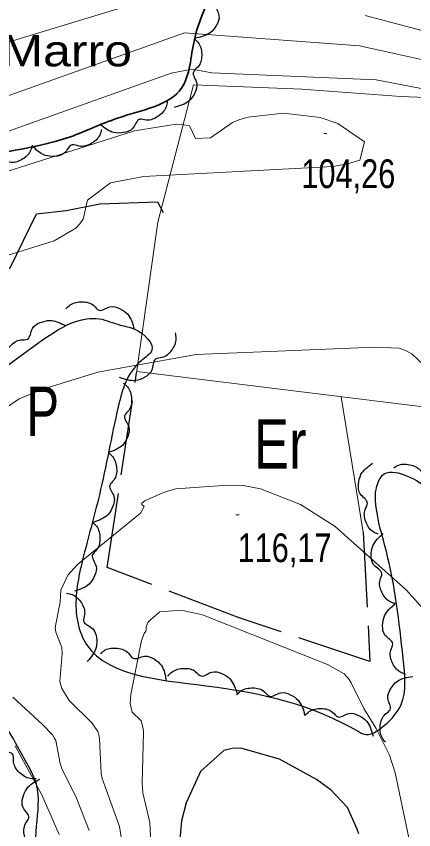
# Model space of a CAD drawing. Extents: x 483843 to 488449, y 4381269 to 4384483.
# Drawn here: x 486707.3 to 486828.4, y 4383075.2 to 4383322.9 of the extents above; entities that cross this region are included whole.
import ezdxf
from ezdxf.enums import TextEntityAlignment as Align

# ---------------------------------------------------------------- set-up
doc = ezdxf.new("R2010")
doc.units = 0
doc.header["$LTSCALE"] = 3.8
doc.linetypes.add('LONG_DASHED', pattern=[7.5, 6, -1.5])
for name, color, linetype, lineweight in [('13', 7, 'Continuous', 35), ('25', 7, 'LONG_DASHED', 25), ('27', 7, 'Continuous', 25), ('51', 7, 'Continuous', 13), ('7', 7, 'Continuous', 13), ('8', 7, 'Continuous', 25), ('9', 7, 'Continuous', 13)]:
    doc.layers.add(name, color=color, linetype=linetype, lineweight=lineweight)
doc.layers.add('31', color=7, linetype='Continuous')
doc.layers.add('5', color=7, linetype='Continuous')

msp = doc.modelspace()

# ---------------------------------------------------------------- linework, layer by layer
at = {"layer": '13'}
msp.add_spline([(486780.88, 4383404.79), (486794.13, 4383455.03), (486806.75, 4383492.74), (486812.33, 4383499.64), (486814.71, 4383503.51), (486819.41, 4383506.81), (486825.21, 4383508.61), (486829.49, 4383508.62), (486831.66, 4383508.22), (486834.79, 4383506.67), (486839.23, 4383502.48), (486841.25, 4383491.57), (486838.33, 4383465.65), (486835.59, 4383431.7), (486834, 4383420.31), (486833.25, 4383414.77), (486832.97, 4383406.37), (486832.3, 4383401.5), (486829.47, 4383397.12), (486823.83, 4383396.67), (486809.94, 4383396.27), (486802.97, 4383396.6), (486796, 4383397.37), (486791.44, 4383398.19), (486788.79, 4383396.8), (486785.88, 4383392.64), (486784.6, 4383386.95), (486784.53, 4383376.98), (486784.84, 4383372.17), (486782.2, 4383361.03), (486774.71, 4383351.45), (486769.08, 4383335.85), (486761.59, 4383315.77), (486757.7, 4383301.05), (486738.21, 4383291.87), (486723.87, 4383286.22), (486684.72, 4383277.1), (486662.99, 4383268.56), (486648.14, 4383263.67), (486639.3, 4383259.75), (486632.91, 4383279.8), (486638.33, 4383280.62), (486654.82, 4383284.96), (486667.34, 4383289.06), (486684.49, 4383297.14), (486691.09, 4383302.53), (486696.41, 4383307.18), (486694.82, 4383316.43), (486684.24, 4383321.46), (486669.01, 4383321.68), (486655.38, 4383318.57), (486643.48, 4383310.34), (486629.22, 4383315.27), (486629.5, 4383324.04), (486622.3, 4383324.82), (486616.85, 4383326.7), (486612.21, 4383337.87), (486614.37, 4383347.45), (486644.42, 4383349.27), (486649.2, 4383384.92), (486651.66, 4383388.63), (486652.89, 4383395.9), (486652.14, 4383401.38), (486671.78, 4383415.81), (486678.55, 4383411.44), (486675.33, 4383401.28), (486669.84, 4383395.35), (486659.1, 4383373.67), (486670.12, 4383362.71), (486675.25, 4383359.48), (486683.36, 4383359.82), (486702.12, 4383364.88), (486729.49, 4383379.19), (486744.12, 4383389.71), (486750.48, 4383393.52), (486749.77, 4383396.53), (486731.96, 4383399.94), (486712.51, 4383419.8), (486725.33, 4383419.24), (486752.3, 4383411.05), (486765.39, 4383408.24), (486770.85, 4383407.04), (486780.7, 4383403.07)], degree=3, dxfattribs=at)
at = {"layer": '25'}
for points in [[(486625.97, 4383203.81), (486659.6, 4383225.99), (486699.78, 4383243.65), (486705.44, 4383246.34), (486713.56, 4383262.73), (486722.5, 4383263.73), (486732.81, 4383265.76), (486750.38, 4383266.41), (486752.13, 4383263.16)], [(486813.02, 4383165.79), (486815.08, 4383126.44), (486775.28, 4383139.77), (486735.05, 4383155.05), (486744, 4383214.28)]]:
    msp.add_lwpolyline(points, dxfattribs=at)
at = {"layer": '27'}
for points in [[(486769.34, 4383336.54), (486770.46, 4383335.16), (486771.14, 4383331.43), (486769.74, 4383328.01), (486768.28, 4383326.57), (486769.09, 4383323.11), (486768.34, 4383320.22), (486766.42, 4383317.89), (486761.75, 4383316.21)], [(486761.71, 4383315.92), (486762.92, 4383314.62), (486763.83, 4383310.94), (486762.66, 4383307.44), (486761.29, 4383305.91), (486762.32, 4383302.51), (486761.75, 4383299.58), (486759.99, 4383297.12), (486755.44, 4383295.15)], [(486753.32, 4383297.03), (486752.97, 4383295.29), (486750.51, 4383292.4), (486746.98, 4383291.31), (486744.94, 4383291.54), (486742.77, 4383288.72), (486740.06, 4383287.47), (486737.04, 4383287.48), (486732.78, 4383290.03)], [(486733.3, 4383288.41), (486732.77, 4383286.72), (486730.04, 4383284.09), (486726.42, 4383283.36), (486724.41, 4383283.79), (486721.97, 4383281.2), (486719.14, 4383280.24), (486716.14, 4383280.55), (486712.16, 4383283.51)], [(486712.16, 4383283.52), (486711.63, 4383281.82), (486708.9, 4383279.19), (486705.28, 4383278.46), (486703.27, 4383278.88), (486700.84, 4383276.29), (486698.02, 4383275.32), (486695.01, 4383275.62), (486691.03, 4383278.59)], [(486722.48, 4383233.81), (486723.78, 4383235.02), (486727.46, 4383235.95), (486730.96, 4383234.79), (486732.5, 4383233.42), (486735.89, 4383234.47), (486738.83, 4383233.9), (486741.29, 4383232.15), (486743.27, 4383227.6)], [(486510.56, 4382972.83), (486592.89, 4382960.7), (486601.82, 4382957.51), (486605.65, 4382949.21), (486605.01, 4382945.38), (486612.67, 4382941.55), (486617.14, 4382941.55), (486645.86, 4382947.29), (486666.92, 4382951.76), (486682.87, 4382958.79), (486691.17, 4382972.2), (486697.55, 4382995.18), (486698.19, 4383013.7), (486700.1, 4383028.38), (486705.21, 4383044.98), (486712.23, 4383062.86), (486713.51, 4383076.27), (486713.51, 4383089.04), (486710.95, 4383094.79), (486707.76, 4383100.53), (486695, 4383117.13), (486669.47, 4383126.71), (486659.9, 4383138.2), (486650.96, 4383150.33), (486637.56, 4383166.93), (486626.71, 4383177.15), (486626.71, 4383182.26), (486685.43, 4383205.88), (486717.33, 4383225.68), (486728.82, 4383230.78), (486732.65, 4383230.78), (486739.03, 4383228.87), (486743.5, 4383227.59), (486748.61, 4383221.21), (486745.41, 4383218.01), (486738.39, 4383203.97), (486732.65, 4383177.15), (486727.55, 4383157.36), (486725.63, 4383141.39), (486727.55, 4383133.73), (486765.2, 4383119.05), (486811.79, 4383105), (486813.06, 4383104.36), (486819.44, 4383106.92), (486824.55, 4383113.3), (486825.19, 4383127.35), (486820.08, 4383159.91), (486816.89, 4383173.96), (486816.89, 4383178.43), (486819.44, 4383183.54), (486826.46, 4383182.9), (486839.23, 4383173.96), (486851.35, 4383158.63), (486851.35, 4383155.44), (486854.55, 4383149.7), (486860.29, 4383146.5), (486874.33, 4383147.78), (486881.35, 4383147.78), (486885.18, 4383146.5), (486885.82, 4383140.12), (486878.16, 4383135.65), (486855.18, 4383117.77), (486850.08, 4383106.92), (486844.33, 4383092.87), (486846.25, 4383073.72), (486850.08, 4383059.67), (486853.27, 4383048.81), (486859.01, 4383039.24), (486866.03, 4383030.3), (486874.97, 4383020.08), (486875.61, 4383011.78), (486873.05, 4382997.74), (486873.05, 4382979.86), (486877.52, 4382957.51), (486880.71, 4382931.33), (486896.03, 4382901.96), (486916.45, 4382878.98), (486920.28, 4382878.34), (486934.96, 4382878.98), (486953.46, 4382889.19), (486954.74, 4382904.52), (486949.64, 4382917.29), (486943.25, 4382926.22), (486931.13, 4382935.16), (486926.66, 4382940.27), (486927.94, 4382947.29), (486935.6, 4382954.32), (486935.6, 4382959.43), (486931.77, 4382975.39), (486917.73, 4383017.53), (486919, 4383028.38)], [(486703.82, 4383217.39), (486703.78, 4383219.16), (486705.55, 4383222.52), (486708.75, 4383224.36), (486710.79, 4383224.59), (486712.28, 4383227.82), (486714.66, 4383229.62), (486717.61, 4383230.28), (486722.32, 4383228.73)], [(486755.72, 4383226.52), (486755.98, 4383224.76), (486754.65, 4383221.2), (486751.71, 4383218.98), (486749.71, 4383218.49), (486748.64, 4383215.1), (486746.51, 4383213.01), (486743.67, 4383211.98), (486738.8, 4383212.93)], [(486739.95, 4383211.23), (486741.26, 4383210.03), (486742.47, 4383206.44), (486741.59, 4383202.85), (486740.34, 4383201.22), (486741.65, 4383197.91), (486741.32, 4383194.94), (486739.76, 4383192.35), (486735.38, 4383190.02)], [(486735.39, 4383190.02), (486736.7, 4383188.82), (486737.92, 4383185.23), (486737.04, 4383181.64), (486735.8, 4383180), (486737.11, 4383176.7), (486736.79, 4383173.73), (486735.24, 4383171.14), (486730.86, 4383168.8)], [(486817.6, 4383165.19), (486816, 4383165.97), (486813.8, 4383169.06), (486813.62, 4383172.75), (486814.33, 4383174.67), (486812.13, 4383177.46), (486811.6, 4383180.4), (486812.34, 4383183.33), (486815.86, 4383186.82)], [(486822.33, 4383185.43), (486823.9, 4383186.26), (486827.69, 4383186.22), (486830.78, 4383184.19), (486831.91, 4383182.48), (486835.46, 4383182.62), (486838.15, 4383181.32), (486840.08, 4383178.99), (486840.83, 4383174.09)], [(486730.52, 4383168.88), (486731.78, 4383167.63), (486732.84, 4383163.98), (486731.81, 4383160.44), (486730.51, 4383158.85), (486731.68, 4383155.5), (486731.22, 4383152.55), (486729.56, 4383150.02), (486725.09, 4383147.87)], [(486822.78, 4383144.05), (486821.12, 4383144.68), (486818.66, 4383147.57), (486818.15, 4383151.22), (486818.7, 4383153.2), (486816.26, 4383155.79), (486815.46, 4383158.67), (486815.95, 4383161.65), (486819.15, 4383165.44)], [(486722.64, 4383147.23), (486724.36, 4383146.82), (486727.17, 4383144.27), (486728.15, 4383140.71), (486727.87, 4383138.68), (486730.62, 4383136.43), (486731.77, 4383133.68), (486731.68, 4383130.66), (486728.99, 4383126.48)], [(486825.88, 4383122.57), (486824.23, 4383123.24), (486821.85, 4383126.2), (486821.43, 4383129.86), (486822.03, 4383131.83), (486819.66, 4383134.48), (486818.94, 4383137.38), (486819.51, 4383140.35), (486822.8, 4383144.05)], [(486733.04, 4383128.89), (486734.47, 4383129.95), (486738.22, 4383130.47), (486741.58, 4383128.94), (486742.96, 4383127.41), (486746.45, 4383128.08), (486749.3, 4383127.2), (486751.56, 4383125.18), (486753.03, 4383120.45)], [(486753.55, 4383121.99), (486754.8, 4383123.25), (486758.43, 4383124.34), (486761.98, 4383123.33), (486763.57, 4383122.03), (486766.92, 4383123.21), (486769.88, 4383122.78), (486772.41, 4383121.13), (486774.59, 4383116.67)], [(486819.85, 4383101.84), (486818.78, 4383103.25), (486818.22, 4383107), (486819.72, 4383110.37), (486821.23, 4383111.76), (486820.53, 4383115.25), (486821.38, 4383118.11), (486823.37, 4383120.39), (486828.09, 4383121.91)], [(486774.47, 4383116.27), (486775.78, 4383117.47), (486779.46, 4383118.39), (486782.96, 4383117.23), (486784.49, 4383115.86), (486787.89, 4383116.89), (486790.82, 4383116.33), (486793.28, 4383114.57), (486795.25, 4383110.02)], [(486795.25, 4383110.01), (486796.56, 4383111.21), (486800.24, 4383112.13), (486803.74, 4383110.95), (486805.27, 4383109.58), (486808.67, 4383110.61), (486811.6, 4383110.03), (486814.05, 4383108.26), (486816.02, 4383103.71)], [(486713.36, 4383090.74), (486711.58, 4383090.77), (486708.28, 4383092.63), (486706.54, 4383095.89), (486706.38, 4383097.94), (486703.2, 4383099.53), (486701.46, 4383101.96), (486700.89, 4383104.93), (486702.59, 4383109.59)], [(486713, 4383068.99), (486711.54, 4383069.99), (486709.83, 4383073.38), (486710.2, 4383077.06), (486711.19, 4383078.85), (486709.43, 4383081.94), (486709.34, 4383084.92), (486710.52, 4383087.71), (486714.52, 4383090.64)]]:
    msp.add_spline(points, degree=3, dxfattribs=at)
at = {"layer": '51'}
for p, q in [((486750.44, 4383260.18), (486744, 4383214.28)), ((486806.31, 4383207.07), (486813.02, 4383165.79))]:
    msp.add_line(p, q, dxfattribs=at)
for points in [[(486750.44, 4383260.18), (486761.32, 4383302.04), (486794.31, 4383300.67), (486824.45, 4383298.51), (486847.1, 4383297.59), (486856.74, 4383295.13), (486862.2, 4383294.15), (486867.82, 4383293.32), (486873.85, 4383289.63), (486879.77, 4383284.29), (486889.44, 4383278.37)], [(486744.07, 4383214.75), (486845.28, 4383202.24), (486894.5, 4383196.44), (486908.29, 4383195.41), (486931.84, 4383194.78)]]:
    msp.add_lwpolyline(points, dxfattribs=at)
at = {"layer": '7'}
for p, q in [((486800.98, 4383287.21), (486801.98, 4383287.21)), ((486774.25, 4383171.06), (486775.25, 4383171.06))]:
    msp.add_line(p, q, dxfattribs=at)
at = {"layer": '8'}
msp.add_lwpolyline([(486811.66, 4383074), (486811.19, 4383075.42), (486808.2, 4383081.94), (486803.3, 4383087.28), (486798.83, 4383090.48), (486787.57, 4383096.71), (486775.78, 4383100.09), (486773.06, 4383099.93), (486770.56, 4383099.29), (486763.5, 4383092.98), (486759.1, 4383083.38), (486757.64, 4383077.9), (486756.78, 4383067.72)], dxfattribs=at)
at = {"layer": '9'}
for points in [[(486747.28, 4383328.04), (486688.74, 4383310.15)], [(486848.97, 4383313.82), (486813.58, 4383323.1)], [(486840.44, 4383307.57), (486811.89, 4383313.92), (486758.63, 4383317.88), (486702.56, 4383297.86)], [(486838.08, 4383299.49), (486816.98, 4383303.5), (486766.94, 4383305.71), (486760.96, 4383306.81), (486754.51, 4383305.59), (486697.49, 4383285.25)], [(486619.7, 4383248.63), (486743.33, 4383288.05), (486756.09, 4383290), (486758.37, 4383289.89), (486760.12, 4383289.5), (486761.93, 4383285.71), (486766.52, 4383285.92), (486773.16, 4383290.59), (486775.48, 4383291.49), (486777.99, 4383292.22), (486788.78, 4383293.41), (486799.94, 4383292.11), (486805.29, 4383290.23), (486813.45, 4383284.71), (486812.04, 4383279.12), (486808.6, 4383278.03), (486803.84, 4383277.14), (486746.13, 4383274.09), (486736.02, 4383272.21), (486729.06, 4383266.93), (486727.68, 4383261.07), (486726.7, 4383259.67), (486725.47, 4383258.38), (486718.87, 4383254.53), (486696.91, 4383247.71)], [(486672.98, 4383163.56), (486671.04, 4383164.92), (486669.76, 4383166.83), (486669.01, 4383168.55), (486667.57, 4383172.89), (486668.27, 4383178.05), (486669.24, 4383179.51), (486670.54, 4383180.97), (486708.23, 4383206.37), (486715.42, 4383209.38), (486732.19, 4383214.56), (486762.18, 4383219.88), (486816.56, 4383222.18), (486824.01, 4383221.81), (486825.94, 4383221.1), (486827.81, 4383220.12), (486841.78, 4383207)], [(486739.79, 4383069.85), (486738.78, 4383076.18), (486733.52, 4383090.85), (486733.21, 4383092.38), (486732.74, 4383102.94), (486732.5, 4383104.06), (486732.19, 4383105.07), (486730.37, 4383107.8), (486723.49, 4383114.6), (486721.23, 4383118.17), (486720.88, 4383119.25), (486720.65, 4383120.37), (486721.3, 4383128.89), (486721.18, 4383130.73), (486719.36, 4383135.4), (486719.26, 4383136.06), (486719.23, 4383136.76), (486720.69, 4383144.47), (486720.95, 4383148.15), (486723.09, 4383152.77), (486726.03, 4383155.98), (486745.23, 4383171.58), (486746.29, 4383173.59), (486745.57, 4383174.24), (486745.56, 4383174.43), (486745.62, 4383174.63), (486746.53, 4383175.37), (486752.22, 4383177.92), (486755.8, 4383178.96), (486771.88, 4383180.15), (486776.49, 4383180.06), (486781.79, 4383179.04), (486793.88, 4383174.24), (486804.5, 4383167.59), (486826.21, 4383148.16), (486838.81, 4383134.09)], [(486750.12, 4383034.67), (486747.98, 4383077.38), (486745.9, 4383086.42), (486745.7, 4383089.38), (486746.09, 4383104.9), (486746.01, 4383106.06), (486745.37, 4383108.34), (486742.68, 4383111), (486742.05, 4383113.69), (486742.2, 4383116.39), (486745.48, 4383132.83), (486746.32, 4383134.99), (486746.8, 4383135.69), (486746.87, 4383135.9), (486746.92, 4383136.12), (486746.89, 4383137), (486747.42, 4383138.26), (486748.33, 4383139.24), (486751.11, 4383141.51), (486757.72, 4383142.06), (486764.06, 4383140.6), (486802.1, 4383125.53), (486807.24, 4383122.71), (486808.73, 4383121), (486809.39, 4383119.94), (486813.19, 4383112.13), (486816.98, 4383106.05), (486821, 4383097.94), (486822.78, 4383092.5), (486828.25, 4383066.45)], [(486729.57, 4383074.98), (486725.69, 4383084.87), (486721.27, 4383093.88), (486720.72, 4383095.37), (486719.36, 4383102.38), (486718.92, 4383103.23), (486718.37, 4383104.08), (486715.37, 4383107.26), (486706.34, 4383115.58)], [(486706.99, 4383100.77), (486715.13, 4383085.83), (486720.37, 4383073.77)]]:
    msp.add_lwpolyline(points, dxfattribs=at)

# ---------------------------------------------------------------- texts
at = {"layer": '31'}
for s, width, p in [('P', 0.75, (486715.39, 4383195.13)), ('Er', 0.8, (486787.75, 4383185.2))]:
    msp.add_text(s, height=15, dxfattribs=dict(at, width=width)).set_placement(p, align=Align.CENTER)
at = {"layer": '5', "width": 1.2}
msp.add_text('Can Marro', height=9.5, dxfattribs=at).set_placement((486670.61, 4383307.66))
at = {"layer": '7', "width": 0.8}
for s, p in [('104,26', (486794.17, 4383270.59)), ('116,17', (486774.75, 4383156.69))]:
    msp.add_text(s, height=8.75, dxfattribs=at).set_placement(p)

doc.saveas('drawing.dxf')
